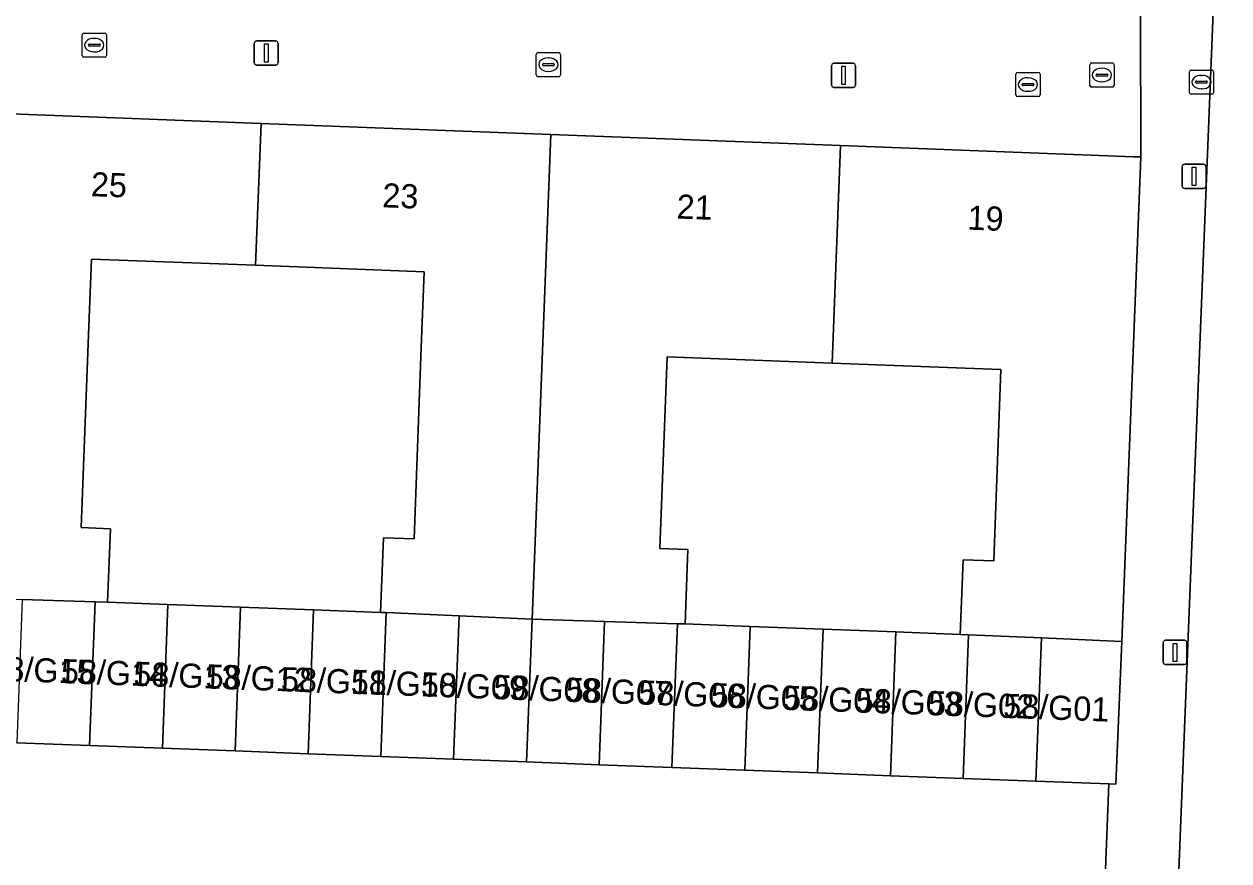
# Model space of a CAD drawing. Extents: x 160786 to 161429, y 386828 to 387485.
# Drawn here: x 161046.7 to 161096.61, y 387097.54 to 387132.21 of the extents above; entities that cross this region are included whole.
import ezdxf

# ---------------------------------------------------------------- set-up
doc = ezdxf.new("R2010")
doc.units = 0
for name, color, linetype in [('IMGEO_Erf', 7, 'Continuous'), ('IMGEO_Kolk', 7, 'Continuous'), ('IMGEO_Lichtmast', 7, 'Continuous'), ('IMGEO_Pand', 7, 'Continuous'), ('IMGEO_Pand_nummerreeks', 7, 'Continuous'), ('IMGEO_Rijbaan_lokaal_open', 7, 'Continuous'), ('IMGEO_Rioolput', 7, 'Continuous'), ('IMGEO_Voetpad_open', 7, 'Continuous')]:
    doc.layers.add(name, color=color, linetype=linetype)

msp = doc.modelspace()

# ---------------------------------------------------------------- linework, layer by layer
at = {"layer": 'IMGEO_Erf'}
msp.add_lwpolyline([(161096.743, 387152.402), (161094.68, 387100.61), (161092.693, 387050.734)], dxfattribs=at)
for points in [[(161063.159, 387118.808), (161063.279, 387121.951), (161056.295, 387122.218), (161049.491, 387122.478), (161049.371, 387119.333), (161049.067, 387111.348), (161050.278, 387111.301), (161050.162, 387108.261), (161052.659, 387108.167), (161055.675, 387108.053), (161058.69, 387107.939), (161061.474, 387107.834), (161061.593, 387110.927), (161062.856, 387110.878)], [(161082.815, 387107.027), (161085.483, 387106.926), (161085.601, 387110.018), (161086.869, 387109.97), (161087.172, 387117.895), (161080.175, 387118.162), (161073.344, 387118.422), (161073.041, 387110.489), (161074.2, 387110.445), (161074.083, 387107.357), (161076.783, 387107.255), (161079.799, 387107.141)]]:
    msp.add_lwpolyline(points, close=True, dxfattribs=at)
at = {"layer": 'IMGEO_Kolk'}
for p, q in [((161049.11, 387130.914), (161049.11, 387131.766)), ((161049.185, 387131.84), (161050.037, 387131.84)), ((161049.598, 387131.62), (161049.623, 387131.62)), ((161050.111, 387131.766), (161050.111, 387130.914)), ((161049.369, 387131.334), (161049.369, 387131.346)), ((161049.807, 387131.297), (161049.409, 387131.297)), ((161049.412, 387131.383), (161049.81, 387131.383)), ((161049.621, 387131.06), (161049.596, 387131.06)), ((161049.853, 387131.346), (161049.853, 387131.334)), ((161067.997, 387131.032), (161068.849, 387131.032)), ((161050.037, 387130.84), (161049.185, 387130.84)), ((161067.922, 387130.106), (161067.922, 387130.958)), ((161068.181, 387130.526), (161068.181, 387130.538)), ((161068.619, 387130.489), (161068.221, 387130.489)), ((161068.224, 387130.575), (161068.622, 387130.575)), ((161068.41, 387130.812), (161068.435, 387130.812)), ((161068.665, 387130.538), (161068.665, 387130.526)), ((161068.923, 387130.958), (161068.923, 387130.106)), ((161068.849, 387130.032), (161067.997, 387130.032)), ((161068.433, 387130.252), (161068.408, 387130.252)), ((161087.788, 387129.282), (161087.788, 387130.134)), ((161087.863, 387130.208), (161088.715, 387130.208)), ((161088.276, 387129.988), (161088.301, 387129.988)), ((161088.789, 387130.134), (161088.789, 387129.282)), ((161088.047, 387129.702), (161088.047, 387129.714)), ((161088.485, 387129.665), (161088.087, 387129.665)), ((161088.09, 387129.751), (161088.488, 387129.751)), ((161088.531, 387129.714), (161088.531, 387129.702)), ((161088.715, 387129.208), (161087.863, 387129.208)), ((161088.299, 387129.428), (161088.274, 387129.428))]:
    msp.add_line(p, q, dxfattribs=at)
for points in [[(161049.11, 387130.914), (161049.11, 387131.766)], [(161049.185, 387131.84), (161050.037, 387131.84)], [(161050.111, 387131.766), (161050.111, 387130.914)], [(161067.997, 387131.032), (161068.849, 387131.032)], [(161050.037, 387130.84), (161049.185, 387130.84)], [(161067.922, 387130.106), (161067.922, 387130.958)], [(161068.923, 387130.958), (161068.923, 387130.106)], [(161068.849, 387130.032), (161067.997, 387130.032)], [(161087.788, 387129.282), (161087.788, 387130.134)], [(161087.863, 387130.208), (161088.715, 387130.208)], [(161088.789, 387130.134), (161088.789, 387129.282)], [(161088.715, 387129.208), (161087.863, 387129.208)]]:
    msp.add_lwpolyline(points, dxfattribs=at)
for centre, radius, start, end in [((161049.187, 387131.764), 0.0765, 91.552, 178.448), ((161049.187, 387131.764), 0.0765, 91.552, 178.448), ((161050.035, 387131.764), 0.0765, 1.552, 88.448), ((161050.035, 387131.764), 0.0765, 1.552, 88.448), ((161049.409, 387131.343), 0.0403, 85.8775, 175.7526), ((161049.406, 387131.333), 0.0366, 178.938, 274.7102), ((161049.81, 387131.34), 0.043, 264.8664, 352.4533), ((161049.814, 387131.345), 0.0386, 1.7309, 96.639), ((161067.999, 387130.956), 0.0765, 91.552, 178.448), ((161067.999, 387130.956), 0.0765, 91.552, 178.448), ((161068.847, 387130.956), 0.0765, 1.552, 88.448), ((161068.847, 387130.956), 0.0765, 1.552, 88.448), ((161049.187, 387130.916), 0.0765, 181.552, 268.448), ((161049.187, 387130.916), 0.0765, 181.552, 268.448), ((161050.035, 387130.916), 0.0765, 271.552, 358.448), ((161050.035, 387130.916), 0.0765, 271.552, 358.448), ((161068.221, 387130.535), 0.0403, 85.8775, 175.7526), ((161068.218, 387130.525), 0.0366, 178.938, 274.7102), ((161068.622, 387130.532), 0.043, 264.8664, 352.4533), ((161068.626, 387130.537), 0.0386, 1.7309, 96.639), ((161067.999, 387130.108), 0.0765, 181.552, 268.448), ((161067.999, 387130.108), 0.0765, 181.552, 268.448), ((161068.847, 387130.108), 0.0765, 271.552, 358.448), ((161068.847, 387130.108), 0.0765, 271.552, 358.448), ((161087.865, 387130.132), 0.0765, 91.552, 178.448), ((161087.865, 387130.132), 0.0765, 91.552, 178.448), ((161088.713, 387130.132), 0.0765, 1.552, 88.448), ((161088.713, 387130.132), 0.0765, 1.552, 88.448), ((161088.087, 387129.711), 0.0403, 85.8775, 175.7526), ((161088.084, 387129.701), 0.0366, 178.938, 274.7102), ((161088.488, 387129.708), 0.043, 264.8664, 352.4533), ((161088.492, 387129.713), 0.0386, 1.7309, 96.639), ((161087.865, 387129.284), 0.0765, 181.552, 268.448), ((161087.865, 387129.284), 0.0765, 181.552, 268.448), ((161088.713, 387129.284), 0.0765, 271.552, 358.448), ((161088.713, 387129.284), 0.0765, 271.552, 358.448)]:
    msp.add_arc(centre, radius, start, end, dxfattribs=at)
for centre, major_axis, ratio, start_param, end_param in [((161049.597, 387131.34), (-0.387, 0.002), 0.722429, 4.712389, 7.853982), ((161049.622, 387131.34), (-0.39, 0.002), 0.717154, 1.570796, 4.712389), ((161068.409, 387130.532), (-0.387, 0.002), 0.722429, 4.712389, 7.853982), ((161068.434, 387130.532), (-0.39, 0.002), 0.717154, 1.570796, 4.712389), ((161088.275, 387129.708), (-0.387, 0.002), 0.722429, 4.712389, 7.853982), ((161088.3, 387129.708), (-0.39, 0.002), 0.717154, 1.570796, 4.712389)]:
    msp.add_ellipse(centre, major_axis=major_axis, ratio=ratio, start_param=start_param, end_param=end_param, dxfattribs=at)
at = {"layer": 'IMGEO_Lichtmast'}
for p, q in [((161056.338, 387131.513), (161057.128, 387131.513)), ((161057.128, 387131.513), (161056.338, 387131.513)), ((161056.238, 387130.613), (161056.238, 387131.413)), ((161056.238, 387131.413), (161056.238, 387130.613)), ((161057.228, 387131.413), (161057.228, 387130.613)), ((161057.228, 387130.613), (161057.228, 387131.413)), ((161057.128, 387130.513), (161056.338, 387130.513)), ((161056.338, 387130.513), (161057.128, 387130.513)), ((161080.153, 387129.687), (161080.153, 387130.487)), ((161080.153, 387130.487), (161080.153, 387129.687)), ((161080.253, 387130.587), (161081.043, 387130.587)), ((161081.043, 387130.587), (161080.253, 387130.587)), ((161081.143, 387130.487), (161081.143, 387129.687)), ((161081.143, 387129.687), (161081.143, 387130.487)), ((161081.043, 387129.587), (161080.253, 387129.587)), ((161080.253, 387129.587), (161081.043, 387129.587)), ((161094.675, 387125.503), (161094.675, 387126.303)), ((161094.675, 387126.303), (161094.675, 387125.503)), ((161094.775, 387126.403), (161095.565, 387126.403)), ((161095.565, 387126.403), (161094.775, 387126.403)), ((161095.665, 387126.303), (161095.665, 387125.503)), ((161095.665, 387125.503), (161095.665, 387126.303)), ((161095.565, 387125.403), (161094.775, 387125.403)), ((161094.775, 387125.403), (161095.565, 387125.403)), ((161093.884, 387105.778), (161093.884, 387106.578)), ((161093.884, 387106.578), (161093.884, 387105.778)), ((161093.984, 387106.678), (161094.774, 387106.678)), ((161094.774, 387106.678), (161093.984, 387106.678)), ((161094.874, 387106.578), (161094.874, 387105.778)), ((161094.874, 387105.778), (161094.874, 387106.578)), ((161094.774, 387105.678), (161093.984, 387105.678)), ((161093.984, 387105.678), (161094.774, 387105.678))]:
    msp.add_line(p, q, dxfattribs=at)
for points in [[(161056.658, 387131.388), (161056.808, 387131.388), (161056.808, 387130.638), (161056.658, 387130.638), (161056.658, 387131.388)], [(161080.573, 387130.462), (161080.723, 387130.462), (161080.723, 387129.712), (161080.573, 387129.712), (161080.573, 387130.462)], [(161095.095, 387126.278), (161095.245, 387126.278), (161095.245, 387125.528), (161095.095, 387125.528), (161095.095, 387126.278)], [(161094.304, 387106.553), (161094.454, 387106.553), (161094.454, 387105.803), (161094.304, 387105.803), (161094.304, 387106.553)]]:
    msp.add_lwpolyline(points, dxfattribs=at)
for centre, start, end in [((161056.338, 387131.413), 90, 180), ((161056.338, 387131.413), 90, 180), ((161057.128, 387131.413), 0, 90), ((161057.128, 387131.413), 360, 90), ((161056.338, 387130.613), 180, 270), ((161056.338, 387130.613), 180, 270), ((161057.128, 387130.613), 270, 0), ((161057.128, 387130.613), 270, 0), ((161080.253, 387130.487), 90, 180), ((161080.253, 387130.487), 90, 180), ((161081.043, 387130.487), 0, 90), ((161081.043, 387130.487), 360, 90), ((161080.253, 387129.687), 180, 270), ((161080.253, 387129.687), 180, 270), ((161081.043, 387129.687), 270, 0), ((161081.043, 387129.687), 270, 0), ((161094.775, 387126.303), 90, 180), ((161094.775, 387126.303), 90, 180), ((161095.565, 387126.303), 0, 90), ((161095.565, 387126.303), 360, 90), ((161094.775, 387125.503), 180, 270), ((161094.775, 387125.503), 180, 270), ((161095.565, 387125.503), 270, 0), ((161095.565, 387125.503), 270, 0), ((161093.984, 387106.578), 90, 180), ((161093.984, 387106.578), 90, 180), ((161094.774, 387106.578), 0, 90), ((161094.774, 387106.578), 360, 90), ((161093.984, 387105.778), 180, 270), ((161093.984, 387105.778), 180, 270), ((161094.774, 387105.778), 270, 0), ((161094.774, 387105.778), 270, 0)]:
    msp.add_arc(centre, 0.1, start, end, dxfattribs=at)
at = {"layer": 'IMGEO_Pand'}
for points in [[(161056.519, 387128.095), (161044.372, 387128.558), (161043.611, 387108.474), (161046.627, 387108.376), (161049.643, 387108.278), (161050.162, 387108.261), (161050.278, 387111.301), (161049.067, 387111.348), (161049.371, 387119.333), (161049.491, 387122.478), (161056.295, 387122.218)], [(161068.52, 387127.638), (161056.519, 387128.095), (161056.295, 387122.218), (161063.279, 387121.951), (161063.159, 387118.808), (161062.856, 387110.878), (161061.593, 387110.927), (161061.474, 387107.834), (161061.706, 387107.824), (161064.721, 387107.692), (161067.753, 387107.56)], [(161068.52, 387127.638), (161067.753, 387107.56), (161070.752, 387107.464), (161073.768, 387107.367), (161074.083, 387107.357), (161074.2, 387110.445), (161073.041, 387110.489), (161073.344, 387118.422), (161080.175, 387118.162), (161080.52, 387127.18)], [(161092.671, 387126.717), (161080.52, 387127.18), (161080.175, 387118.162), (161087.172, 387117.895), (161086.869, 387109.97), (161085.601, 387110.018), (161085.483, 387106.926), (161085.83, 387106.911), (161088.845, 387106.78), (161092.172, 387106.635), (161092.971, 387126.705)], [(161046.403, 387102.435), (161049.418, 387102.321), (161049.643, 387108.278), (161046.627, 387108.376)], [(161049.418, 387102.321), (161052.434, 387102.207), (161052.659, 387108.167), (161050.162, 387108.261), (161049.643, 387108.278)], [(161052.434, 387102.207), (161055.449, 387102.093), (161055.675, 387108.053), (161052.659, 387108.167)], [(161058.69, 387107.939), (161055.675, 387108.053), (161055.449, 387102.093), (161058.465, 387101.979)], [(161061.706, 387107.824), (161061.474, 387107.834), (161058.69, 387107.939), (161058.465, 387101.979), (161061.48, 387101.865)], [(161061.48, 387101.865), (161064.496, 387101.751), (161064.721, 387107.692), (161061.706, 387107.824)], [(161064.496, 387101.751), (161067.512, 387101.637), (161067.753, 387107.56), (161064.721, 387107.692)], [(161067.512, 387101.637), (161070.527, 387101.523), (161070.752, 387107.464), (161067.753, 387107.56)], [(161073.768, 387107.367), (161070.752, 387107.464), (161070.527, 387101.523), (161073.543, 387101.409)], [(161073.543, 387101.409), (161076.558, 387101.295), (161076.783, 387107.255), (161074.083, 387107.357), (161073.768, 387107.367)], [(161076.558, 387101.295), (161079.574, 387101.181), (161079.799, 387107.141), (161076.783, 387107.255)], [(161079.574, 387101.181), (161082.589, 387101.067), (161082.815, 387107.027), (161079.799, 387107.141)], [(161085.83, 387106.911), (161085.483, 387106.926), (161082.815, 387107.027), (161082.589, 387101.067), (161085.605, 387100.953)], [(161085.605, 387100.953), (161088.62, 387100.839), (161088.845, 387106.78), (161085.83, 387106.911)], [(161092.172, 387106.635), (161088.845, 387106.78), (161088.62, 387100.839), (161091.636, 387100.725), (161091.936, 387100.713)]]:
    msp.add_lwpolyline(points, close=True, dxfattribs=at)
at = {"layer": 'IMGEO_Rijbaan_lokaal_open'}
msp.add_lwpolyline([(161090.543, 387072.746), (161091.636, 387100.725), (161088.62, 387100.839), (161085.605, 387100.953), (161082.589, 387101.067), (161079.574, 387101.181), (161076.558, 387101.295), (161073.543, 387101.409), (161070.527, 387101.523), (161067.512, 387101.637), (161064.496, 387101.751), (161061.48, 387101.865), (161058.465, 387101.979), (161055.449, 387102.093), (161052.434, 387102.207), (161049.418, 387102.321), (161046.403, 387102.435), (161043.387, 387102.549), (161043.394, 387100.73), (161042.709, 387083.01)], dxfattribs=at)
at = {"layer": 'IMGEO_Rioolput'}
for p, q in [((161090.853, 387129.674), (161090.853, 387130.526)), ((161090.928, 387130.6), (161091.78, 387130.6)), ((161091.854, 387130.526), (161091.854, 387129.674)), ((161091.112, 387130.094), (161091.112, 387130.106)), ((161091.55, 387130.057), (161091.152, 387130.057)), ((161091.155, 387130.143), (161091.553, 387130.143)), ((161091.341, 387130.38), (161091.366, 387130.38)), ((161091.596, 387130.106), (161091.596, 387130.094)), ((161094.977, 387129.381), (161094.977, 387130.233)), ((161095.052, 387130.307), (161095.904, 387130.307)), ((161095.465, 387130.087), (161095.49, 387130.087)), ((161095.978, 387130.233), (161095.978, 387129.381)), ((161091.78, 387129.6), (161090.928, 387129.6)), ((161091.364, 387129.82), (161091.339, 387129.82)), ((161095.236, 387129.801), (161095.236, 387129.813)), ((161095.674, 387129.764), (161095.276, 387129.764)), ((161095.279, 387129.85), (161095.677, 387129.85)), ((161095.488, 387129.527), (161095.463, 387129.527)), ((161095.72, 387129.813), (161095.72, 387129.801)), ((161095.904, 387129.307), (161095.052, 387129.307))]:
    msp.add_line(p, q, dxfattribs=at)
for points in [[(161090.853, 387129.674), (161090.853, 387130.526)], [(161090.928, 387130.6), (161091.78, 387130.6)], [(161091.854, 387130.526), (161091.854, 387129.674)], [(161094.977, 387129.381), (161094.977, 387130.233)], [(161095.052, 387130.307), (161095.904, 387130.307)], [(161095.978, 387130.233), (161095.978, 387129.381)], [(161091.78, 387129.6), (161090.928, 387129.6)], [(161095.904, 387129.307), (161095.052, 387129.307)]]:
    msp.add_lwpolyline(points, dxfattribs=at)
for centre, radius, start, end in [((161090.93, 387130.524), 0.0765, 91.552, 178.448), ((161090.93, 387130.524), 0.0765, 91.552, 178.448), ((161091.778, 387130.524), 0.0765, 1.552, 88.448), ((161091.778, 387130.524), 0.0765, 1.552, 88.448), ((161091.152, 387130.103), 0.0403, 85.8775, 175.7526), ((161091.149, 387130.093), 0.0366, 178.938, 274.7102), ((161091.553, 387130.1), 0.043, 264.8664, 352.4533), ((161091.557, 387130.105), 0.0386, 1.7309, 96.639), ((161095.054, 387130.231), 0.0765, 91.552, 178.448), ((161095.054, 387130.231), 0.0765, 91.552, 178.448), ((161095.902, 387130.231), 0.0765, 1.552, 88.448), ((161095.902, 387130.231), 0.0765, 1.552, 88.448), ((161090.93, 387129.676), 0.0765, 181.552, 268.448), ((161090.93, 387129.676), 0.0765, 181.552, 268.448), ((161091.778, 387129.676), 0.0765, 271.552, 358.448), ((161091.778, 387129.676), 0.0765, 271.552, 358.448), ((161095.276, 387129.81), 0.0403, 85.8775, 175.7526), ((161095.273, 387129.8), 0.0366, 178.938, 274.7102), ((161095.677, 387129.807), 0.043, 264.8664, 352.4533), ((161095.681, 387129.812), 0.0386, 1.7309, 96.639), ((161095.054, 387129.383), 0.0765, 181.552, 268.448), ((161095.054, 387129.383), 0.0765, 181.552, 268.448), ((161095.902, 387129.383), 0.0765, 271.552, 358.448), ((161095.902, 387129.383), 0.0765, 271.552, 358.448)]:
    msp.add_arc(centre, radius, start, end, dxfattribs=at)
for centre, major_axis, ratio, start_param, end_param in [((161091.34, 387130.1), (-0.387, 0.002), 0.722429, 4.712389, 7.853982), ((161091.365, 387130.1), (-0.39, 0.002), 0.717154, 1.570796, 4.712389), ((161095.464, 387129.807), (-0.387, 0.002), 0.722429, 4.712389, 7.853982), ((161095.489, 387129.807), (-0.39, 0.002), 0.717154, 1.570796, 4.712389)]:
    msp.add_ellipse(centre, major_axis=major_axis, ratio=ratio, start_param=start_param, end_param=end_param, dxfattribs=at)
at = {"layer": 'IMGEO_Voetpad_open'}
for points in [[(161092.693, 387050.734), (161094.68, 387100.61), (161096.743, 387152.402)], [(161092.948, 387132.584), (161092.971, 387126.705), (161092.172, 387106.635), (161091.936, 387100.713), (161091.636, 387100.725), (161090.543, 387072.746)]]:
    msp.add_lwpolyline(points, dxfattribs=at)
msp.add_lwpolyline([(161092.948, 387132.584), (161087.709, 387132.788), (161086.71, 387132.827), (161086.258, 387132.845), (161074.979, 387133.284), (161073.98, 387133.323), (161073.624, 387133.337), (161063.737, 387133.722), (161062.738, 387133.761), (161062.414, 387133.774), (161051.003, 387134.218), (161050.004, 387134.257), (161049.591, 387134.273), (161044.706, 387134.463), (161039.235, 387134.676), (161035.238, 387134.832), (161034.974, 387128.863), (161039.845, 387128.705), (161044.372, 387128.558), (161056.519, 387128.095), (161068.52, 387127.638), (161080.52, 387127.18), (161092.671, 387126.717), (161092.971, 387126.705)], close=True, dxfattribs=at)

# ---------------------------------------------------------------- texts
at = {"layer": 'IMGEO_Pand_nummerreeks'}
for s, rotation, p in [('25', 357.817, (161049.458, 387125.082)), ('23', 357.817, (161061.533, 387124.622)), ('21', 357.8171, (161073.721, 387124.157)), ('19', 357.8171, (161085.774, 387123.697)), ('58/G15', 357.8881, (161045.217, 387105.02)), ('58/G14', 357.8881, (161048.218, 387104.909)), ('58/G13', 357.8881, (161051.219, 387104.799)), ('58/G12', 357.8881, (161054.214, 387104.688)), ('58/G11', 357.8881, (161057.332, 387104.573)), ('58/G10', 357.8881, (161060.226, 387104.467)), ('58/G09', 357.8881, (161063.13, 387104.36)), ('58/G08', 357.8881, (161066.138, 387104.249)), ('58/G07', 357.8881, (161069.136, 387104.138)), ('58/G06', 357.8881, (161072.137, 387104.027)), ('58/G05', 357.8881, (161075.139, 387103.917)), ('58/G04', 357.8881, (161078.14, 387103.806)), ('58/G03', 357.8881, (161081.141, 387103.695)), ('58/G02', 357.8881, (161084.136, 387103.585)), ('58/G01', 357.8881, (161087.254, 387103.47))]:
    msp.add_text(s, height=1, rotation=rotation, dxfattribs=at).set_placement(p)

doc.saveas('drawing.dxf')
